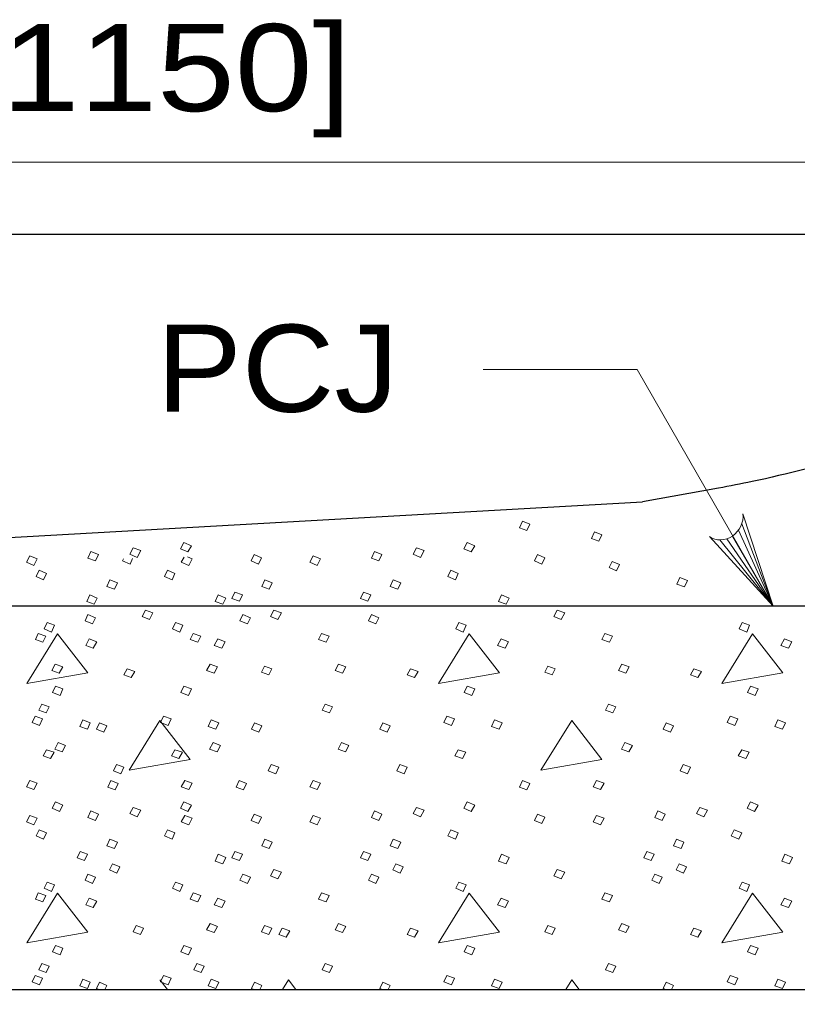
# Model space of a CAD drawing. Extents: x -1431.2 to -1397.2, y -1045.1 to -1001.1.
# Drawn here: x -1423.56 to -1422.141, y -1043.619 to -1041.85 of the extents above; entities that cross this region are included whole.
import ezdxf

# ---------------------------------------------------------------- set-up
doc = ezdxf.new("R2010")
doc.units = 0
doc.header["$LTSCALE"] = 0.064
doc.layers.add('1', color=7, linetype='Continuous', lineweight=13)

msp = doc.modelspace()

# ---------------------------------------------------------------- linework, layer by layer
at = {"layer": '1'}
for p, q in [((-1421.35642, -1042.111), (-1425.81283, -1042.111)), ((-1422.43383, -1042.48883), (-1422.71458, -1042.48883)), ((-1422.18592, -1042.9205), (-1422.43383, -1042.48883)), ((-1422.24292, -1042.77033), (-1422.18592, -1042.9205)), ((-1422.27042, -1042.79767), (-1422.18592, -1042.9205)), ((-1422.25992, -1042.79242), (-1422.18592, -1042.9205)), ((-1422.24883, -1042.78158), (-1422.18592, -1042.9205)), ((-1422.28267, -1042.79958), (-1422.18592, -1042.9205)), ((-1423.29, -1043.61933), (-1423.30367, -1043.60183)), ((-1423.0695, -1043.60183), (-1423.08042, -1043.61933)), ((-1423.05592, -1043.61933), (-1423.0695, -1043.60183)), ((-1422.553, -1043.60183), (-1422.56392, -1043.61933)), ((-1422.53942, -1043.61933), (-1422.553, -1043.60183))]:
    msp.add_line(p, q, dxfattribs=at)
at = {"layer": '1', "lineweight": 25}
for p, q in [((-1422.28533, -1042.70533), (-1422.42375, -1042.73033)), ((-1425.81283, -1042.9205), (-1422.42375, -1042.73033)), ((-1420.649, -1042.9205), (-1425.81283, -1042.9205))]:
    msp.add_line(p, q, dxfattribs=at)
for points in [[(-1421.35642, -1042.24275), (-1422.37992, -1042.24275), (-1425.79833, -1042.24275)], [(-1426.53858, -1043.13475), (-1426.53858, -1043.61933), (-1420.649, -1043.61933)]]:
    msp.add_lwpolyline(points, dxfattribs=at)
at = {"layer": '1'}
for points in [[(-1422.241, -1042.75167), (-1422.18592, -1042.9205), (-1422.30192, -1042.79317)], [(-1423.25333, -1042.83058), (-1423.24475, -1042.83367), (-1423.25108, -1042.84592), (-1423.26467, -1042.84017), (-1423.25942, -1042.83075)], [(-1423.35333, -1042.83358), (-1423.358, -1042.84342), (-1423.37158, -1042.83775), (-1423.36992, -1042.83408)], [(-1423.41467, -1043.61933), (-1423.41933, -1043.61733), (-1423.41392, -1043.60592)], [(-1423.41392, -1043.60592), (-1423.40033, -1043.61167), (-1423.40392, -1043.61933)], [(-1423.13225, -1043.61933), (-1423.13692, -1043.61733), (-1423.1315, -1043.60592)], [(-1423.1315, -1043.60592), (-1423.11783, -1043.61167), (-1423.1215, -1043.61933)], [(-1422.89817, -1043.61933), (-1422.90283, -1043.61733), (-1422.89733, -1043.60592)], [(-1422.89733, -1043.60592), (-1422.88375, -1043.61167), (-1422.88742, -1043.61933)], [(-1422.38167, -1043.61933), (-1422.38625, -1043.61733), (-1422.38083, -1043.60592)], [(-1422.38083, -1043.60592), (-1422.36725, -1043.61167), (-1422.37083, -1043.61933)]]:
    msp.add_lwpolyline(points, dxfattribs=at)
for points in [[(-1422.64275, -1042.76517), (-1422.62917, -1042.77092), (-1422.63458, -1042.78233), (-1422.64817, -1042.77742)], [(-1422.51142, -1042.78483), (-1422.49783, -1042.7905), (-1422.50325, -1042.80192), (-1422.51683, -1042.797)], [(-1423.35225, -1042.81408), (-1423.33867, -1042.819), (-1423.345, -1042.83125), (-1423.35858, -1042.8255)], [(-1423.25983, -1042.80433), (-1423.24625, -1042.81), (-1423.25258, -1042.82142), (-1423.26617, -1042.81575)], [(-1422.83575, -1042.81408), (-1422.82217, -1042.819), (-1422.8285, -1042.83125), (-1422.84208, -1042.8255)], [(-1422.74333, -1042.80433), (-1422.72975, -1042.81), (-1422.73608, -1042.82142), (-1422.74967, -1042.81575)], [(-1423.54075, -1042.82875), (-1423.52717, -1042.83367), (-1423.5335, -1042.84592), (-1423.54708, -1042.84017)], [(-1423.42933, -1042.82058), (-1423.41567, -1042.82633), (-1423.42117, -1042.83775), (-1423.43475, -1042.83283)], [(-1423.13208, -1042.82633), (-1423.1185, -1042.832), (-1423.12392, -1042.84342), (-1423.1375, -1042.83775)], [(-1423.02425, -1042.82875), (-1423.01067, -1042.83367), (-1423.017, -1042.84592), (-1423.03058, -1042.84017)], [(-1422.91275, -1042.82058), (-1422.89917, -1042.82633), (-1422.90458, -1042.83775), (-1422.91817, -1042.83283)], [(-1422.61558, -1042.82633), (-1422.60192, -1042.832), (-1422.60742, -1042.84342), (-1422.621, -1042.83775)], [(-1422.47933, -1042.83858), (-1422.46575, -1042.84433), (-1422.47117, -1042.85575), (-1422.48475, -1042.85)], [(-1423.52383, -1042.85483), (-1423.51025, -1042.86058), (-1423.51567, -1042.872), (-1423.52925, -1042.86625)], [(-1423.28975, -1042.85483), (-1423.27617, -1042.86058), (-1423.28158, -1042.872), (-1423.29517, -1042.86625)], [(-1422.77325, -1042.85483), (-1422.75967, -1042.86058), (-1422.76508, -1042.872), (-1422.77867, -1042.86625)], [(-1422.35567, -1042.86783), (-1422.34208, -1042.8735), (-1422.3475, -1042.88492), (-1422.36108, -1042.88008)], [(-1423.39483, -1042.872), (-1423.38125, -1042.87767), (-1423.38667, -1042.88908), (-1423.40033, -1042.88425)], [(-1423.11242, -1042.872), (-1423.09883, -1042.87767), (-1423.10425, -1042.88908), (-1423.11783, -1042.88425)], [(-1422.87833, -1042.872), (-1422.86475, -1042.87767), (-1422.87017, -1042.88908), (-1422.88375, -1042.88425)], [(-1423.43142, -1042.89975), (-1423.41783, -1042.90542), (-1423.42325, -1042.91683), (-1423.43683, -1042.91192)], [(-1423.19733, -1042.89975), (-1423.18375, -1042.90542), (-1423.18917, -1042.91683), (-1423.20275, -1042.91192)], [(-1423.16683, -1042.89483), (-1423.15325, -1042.89975), (-1423.15867, -1042.91117), (-1423.17225, -1042.90625)], [(-1422.93267, -1042.89483), (-1422.91908, -1042.89975), (-1422.92458, -1042.91117), (-1422.93817, -1042.90625)], [(-1422.68075, -1042.89975), (-1422.66717, -1042.90542), (-1422.67267, -1042.91683), (-1422.68625, -1042.91192)], [(-1423.43475, -1042.93558), (-1423.42117, -1042.94133), (-1423.42658, -1042.95275), (-1423.44017, -1042.947)], [(-1423.32992, -1042.92742), (-1423.31633, -1042.93233), (-1423.32267, -1042.94458), (-1423.33625, -1042.93883)], [(-1423.15233, -1042.93558), (-1423.13875, -1042.94133), (-1423.14417, -1042.95275), (-1423.15775, -1042.947)], [(-1423.09583, -1042.92742), (-1423.08225, -1042.93233), (-1423.08858, -1042.94458), (-1423.10217, -1042.93883)], [(-1422.91817, -1042.93558), (-1422.90458, -1042.94133), (-1422.91008, -1042.95275), (-1422.92367, -1042.947)], [(-1422.57925, -1042.92742), (-1422.56567, -1042.93233), (-1422.57208, -1042.94458), (-1422.58567, -1042.93883)], [(-1423.50933, -1042.95025), (-1423.49575, -1042.95517), (-1423.50117, -1042.96742), (-1423.51475, -1042.96167)], [(-1423.27525, -1042.95025), (-1423.26167, -1042.95517), (-1423.26708, -1042.96742), (-1423.28067, -1042.96167)], [(-1422.75875, -1042.95025), (-1422.74517, -1042.95517), (-1422.75058, -1042.96742), (-1422.76417, -1042.96167)], [(-1422.24217, -1042.95025), (-1422.22858, -1042.95517), (-1422.234, -1042.96742), (-1422.24767, -1042.96167)], [(-1423.49033, -1042.97067), (-1423.5465, -1043.06117), (-1423.435, -1043.04158)], [(-1423.52533, -1042.96983), (-1423.51175, -1042.97475), (-1423.51717, -1042.98617), (-1423.53075, -1042.98125)], [(-1423.24292, -1042.96983), (-1423.22933, -1042.97475), (-1423.23475, -1042.98617), (-1423.24833, -1042.98125)], [(-1423.00883, -1042.96983), (-1422.99525, -1042.97475), (-1423.00067, -1042.98617), (-1423.01425, -1042.98125)], [(-1422.73967, -1042.97067), (-1422.79583, -1043.06117), (-1422.68442, -1043.04158)], [(-1422.49233, -1042.96983), (-1422.47867, -1042.97475), (-1422.48417, -1042.98617), (-1422.49775, -1042.98125)], [(-1422.22317, -1042.97067), (-1422.27933, -1043.06117), (-1422.16792, -1043.04158)], [(-1423.43233, -1042.97967), (-1423.41875, -1042.98533), (-1423.42508, -1042.99675), (-1423.43867, -1042.99183)], [(-1423.19825, -1042.97967), (-1423.18467, -1042.98533), (-1423.191, -1042.99675), (-1423.20458, -1042.99183)], [(-1422.68167, -1042.97967), (-1422.66808, -1042.98533), (-1422.67442, -1042.99675), (-1422.688, -1042.99183)], [(-1422.16517, -1042.97967), (-1422.15158, -1042.98533), (-1422.15792, -1042.99675), (-1422.1715, -1042.99183)], [(-1423.4945, -1043.02608), (-1423.48092, -1043.031), (-1423.48733, -1043.04242), (-1423.50092, -1043.0375)], [(-1423.21208, -1043.02608), (-1423.1985, -1043.031), (-1423.20483, -1043.04242), (-1423.21842, -1043.0375)], [(-1422.978, -1043.02608), (-1422.96442, -1043.031), (-1422.97075, -1043.04242), (-1422.98433, -1043.0375)], [(-1422.4615, -1043.02608), (-1422.44792, -1043.031), (-1422.45425, -1043.04242), (-1422.46783, -1043.0375)], [(-1423.36317, -1043.03425), (-1423.34958, -1043.03917), (-1423.35592, -1043.05058), (-1423.3695, -1043.04567)], [(-1423.113, -1043.02942), (-1423.09942, -1043.03425), (-1423.10492, -1043.04567), (-1423.1185, -1043.04083)], [(-1422.84667, -1043.03425), (-1422.833, -1043.03917), (-1422.83933, -1043.05058), (-1422.853, -1043.04567)], [(-1422.5965, -1043.02942), (-1422.58292, -1043.03425), (-1422.58833, -1043.04567), (-1422.60192, -1043.04083)], [(-1422.33008, -1043.03425), (-1422.3165, -1043.03917), (-1422.32283, -1043.05058), (-1422.33642, -1043.04567)], [(-1423.49392, -1043.06608), (-1423.48033, -1043.071), (-1423.48575, -1043.08317), (-1423.49933, -1043.0775)], [(-1423.25983, -1043.06608), (-1423.24625, -1043.071), (-1423.25167, -1043.08317), (-1423.26525, -1043.0775)], [(-1422.74333, -1043.06608), (-1422.72975, -1043.071), (-1422.73517, -1043.08317), (-1422.74875, -1043.0775)], [(-1422.22675, -1043.06608), (-1422.21317, -1043.071), (-1422.21867, -1043.08317), (-1422.23225, -1043.0775)], [(-1423.519, -1043.09867), (-1423.50542, -1043.10358), (-1423.51083, -1043.115), (-1423.52442, -1043.11008)], [(-1423.0025, -1043.09867), (-1422.98892, -1043.10358), (-1422.99433, -1043.115), (-1423.00792, -1043.11008)], [(-1422.486, -1043.09867), (-1422.47233, -1043.10358), (-1422.47783, -1043.115), (-1422.49142, -1043.11008)], [(-1423.53108, -1043.12075), (-1423.5175, -1043.12558), (-1423.52292, -1043.13783), (-1423.5365, -1043.13217)], [(-1423.44408, -1043.12725), (-1423.4305, -1043.13292), (-1423.43592, -1043.14433), (-1423.4495, -1043.1395)], [(-1423.41392, -1043.13292), (-1423.40033, -1043.13867), (-1423.40575, -1043.15008), (-1423.41933, -1043.14433)], [(-1423.30367, -1043.12883), (-1423.35983, -1043.21942), (-1423.24833, -1043.19983)], [(-1423.297, -1043.12075), (-1423.28342, -1043.12558), (-1423.28883, -1043.13783), (-1423.30242, -1043.13217)], [(-1423.21, -1043.12725), (-1423.19642, -1043.13292), (-1423.20183, -1043.14433), (-1423.21542, -1043.1395)], [(-1423.1315, -1043.13292), (-1423.11783, -1043.13867), (-1423.12333, -1043.15008), (-1423.13692, -1043.14433)], [(-1422.89733, -1043.13292), (-1422.88375, -1043.13867), (-1422.88917, -1043.15008), (-1422.90283, -1043.14433)], [(-1422.7805, -1043.12075), (-1422.76683, -1043.12558), (-1422.77233, -1043.13783), (-1422.78592, -1043.13217)], [(-1422.6935, -1043.12725), (-1422.67992, -1043.13292), (-1422.68533, -1043.14433), (-1422.69892, -1043.1395)], [(-1422.553, -1043.12883), (-1422.60917, -1043.21942), (-1422.49775, -1043.19983)], [(-1422.38083, -1043.13292), (-1422.36725, -1043.13867), (-1422.37267, -1043.15008), (-1422.38625, -1043.14433)], [(-1422.26392, -1043.12075), (-1422.25033, -1043.12558), (-1422.25575, -1043.13783), (-1422.26942, -1043.13217)], [(-1422.17692, -1043.12725), (-1422.16333, -1043.13292), (-1422.16883, -1043.14433), (-1422.18242, -1043.1395)], [(-1423.48908, -1043.16883), (-1423.4755, -1043.17458), (-1423.48183, -1043.186), (-1423.49542, -1043.18108)], [(-1423.20667, -1043.16883), (-1423.19308, -1043.17458), (-1423.19942, -1043.186), (-1423.213, -1043.18108)], [(-1422.97258, -1043.16883), (-1422.959, -1043.17458), (-1422.96533, -1043.186), (-1422.97892, -1043.18108)], [(-1422.45608, -1043.16883), (-1422.44242, -1043.17458), (-1422.44883, -1043.186), (-1422.46242, -1043.18108)], [(-1423.51025, -1043.18192), (-1423.49667, -1043.18675), (-1423.503, -1043.19817), (-1423.51658, -1043.19325)], [(-1423.27617, -1043.18192), (-1423.26258, -1043.18675), (-1423.26892, -1043.19817), (-1423.2825, -1043.19325)], [(-1422.75967, -1043.18192), (-1422.746, -1043.18675), (-1422.75233, -1043.19817), (-1422.766, -1043.19325)], [(-1422.24308, -1043.18192), (-1422.2295, -1043.18675), (-1422.23583, -1043.19817), (-1422.24942, -1043.19325)], [(-1423.38308, -1043.20875), (-1423.3695, -1043.21367), (-1423.37492, -1043.22592), (-1423.3885, -1043.22025)], [(-1423.10067, -1043.20875), (-1423.08708, -1043.21367), (-1423.0925, -1043.22592), (-1423.10608, -1043.22025)], [(-1422.86658, -1043.20875), (-1422.853, -1043.21367), (-1422.85842, -1043.22592), (-1422.872, -1043.22025)], [(-1422.35, -1043.20875), (-1422.33642, -1043.21367), (-1422.34192, -1043.22592), (-1422.3555, -1043.22025)], [(-1423.54075, -1043.23817), (-1423.52717, -1043.243), (-1423.5335, -1043.25442), (-1423.54708, -1043.24958)], [(-1423.39333, -1043.23817), (-1423.37975, -1043.24383), (-1423.38517, -1043.25525), (-1423.39875, -1043.25042)], [(-1423.25833, -1043.23817), (-1423.24475, -1043.243), (-1423.25108, -1043.25442), (-1423.26467, -1043.24958)], [(-1423.15925, -1043.23817), (-1423.14567, -1043.24383), (-1423.15108, -1043.25525), (-1423.16467, -1043.25042)], [(-1423.02425, -1043.23817), (-1423.01067, -1043.243), (-1423.017, -1043.25442), (-1423.03058, -1043.24958)], [(-1422.64275, -1043.23817), (-1422.62917, -1043.24383), (-1422.63458, -1043.25525), (-1422.64817, -1043.25042)], [(-1422.50775, -1043.23817), (-1422.49408, -1043.243), (-1422.50042, -1043.25442), (-1422.51408, -1043.24958)], [(-1423.49392, -1043.27725), (-1423.48033, -1043.283), (-1423.48667, -1043.29442), (-1423.50025, -1043.28867)], [(-1423.35225, -1043.28708), (-1423.33867, -1043.292), (-1423.345, -1043.30417), (-1423.35858, -1043.2985)], [(-1423.25983, -1043.27725), (-1423.24625, -1043.283), (-1423.25258, -1043.29442), (-1423.26617, -1043.28867)], [(-1422.83575, -1043.28708), (-1422.82217, -1043.292), (-1422.8285, -1043.30417), (-1422.84208, -1043.2985)], [(-1422.74333, -1043.27725), (-1422.72975, -1043.283), (-1422.73608, -1043.29442), (-1422.74967, -1043.28867)], [(-1422.31925, -1043.28708), (-1422.30558, -1043.292), (-1422.312, -1043.30417), (-1422.32558, -1043.2985)], [(-1422.22675, -1043.27725), (-1422.21317, -1043.283), (-1422.2195, -1043.29442), (-1422.23317, -1043.28867)], [(-1423.54075, -1043.30175), (-1423.52717, -1043.30667), (-1423.5335, -1043.31892), (-1423.54708, -1043.31317)], [(-1423.42933, -1043.29358), (-1423.41567, -1043.29933), (-1423.42117, -1043.31075), (-1423.43475, -1043.30583)], [(-1423.25833, -1043.30175), (-1423.24475, -1043.30667), (-1423.25108, -1043.31892), (-1423.26467, -1043.31317)], [(-1423.13208, -1043.29933), (-1423.1185, -1043.305), (-1423.12392, -1043.31642), (-1423.1375, -1043.31075)], [(-1423.02425, -1043.30175), (-1423.01067, -1043.30667), (-1423.017, -1043.31892), (-1423.03058, -1043.31317)], [(-1422.91275, -1043.29358), (-1422.89917, -1043.29933), (-1422.90458, -1043.31075), (-1422.91817, -1043.30583)], [(-1422.61558, -1043.29933), (-1422.60192, -1043.305), (-1422.60742, -1043.31642), (-1422.621, -1043.31075)], [(-1422.50775, -1043.30175), (-1422.49408, -1043.30667), (-1422.50042, -1043.31892), (-1422.51408, -1043.31317)], [(-1422.39625, -1043.29358), (-1422.38267, -1043.29933), (-1422.38808, -1043.31075), (-1422.40167, -1043.30583)], [(-1423.52383, -1043.32783), (-1423.51025, -1043.33358), (-1423.51567, -1043.345), (-1423.52925, -1043.33925)], [(-1423.28975, -1043.32783), (-1423.27617, -1043.33358), (-1423.28158, -1043.345), (-1423.29517, -1043.33925)], [(-1422.77325, -1043.32783), (-1422.75967, -1043.33358), (-1422.76508, -1043.345), (-1422.77867, -1043.33925)], [(-1422.25667, -1043.32783), (-1422.24308, -1043.33358), (-1422.2485, -1043.345), (-1422.26217, -1043.33925)], [(-1423.39483, -1043.345), (-1423.38125, -1043.35067), (-1423.38667, -1043.36208), (-1423.40033, -1043.35717)], [(-1423.11242, -1043.345), (-1423.09883, -1043.35067), (-1423.10425, -1043.36208), (-1423.11783, -1043.35717)], [(-1422.87833, -1043.345), (-1422.86475, -1043.35067), (-1422.87017, -1043.36208), (-1422.88375, -1043.35717)], [(-1422.36183, -1043.345), (-1422.34825, -1043.35067), (-1422.35367, -1043.36208), (-1422.36725, -1043.35717)], [(-1423.44925, -1043.36783), (-1423.43567, -1043.37267), (-1423.44108, -1043.38408), (-1423.45467, -1043.37925)], [(-1423.19733, -1043.37267), (-1423.18375, -1043.37842), (-1423.18917, -1043.38983), (-1423.20275, -1043.38492)], [(-1423.16683, -1043.36783), (-1423.15325, -1043.37267), (-1423.15867, -1043.38408), (-1423.17225, -1043.37925)], [(-1422.93267, -1043.36783), (-1422.91908, -1043.37267), (-1422.92458, -1043.38408), (-1422.93817, -1043.37925)], [(-1422.68075, -1043.37267), (-1422.66717, -1043.37842), (-1422.67267, -1043.38983), (-1422.68625, -1043.38492)], [(-1422.41617, -1043.36783), (-1422.40258, -1043.37267), (-1422.408, -1043.38408), (-1422.42158, -1043.37925)], [(-1422.16425, -1043.37267), (-1422.15067, -1043.37842), (-1422.15608, -1043.38983), (-1422.16967, -1043.38492)], [(-1423.39033, -1043.38983), (-1423.37675, -1043.3955), (-1423.38217, -1043.40692), (-1423.39575, -1043.40125)], [(-1422.87383, -1043.38983), (-1422.86025, -1043.3955), (-1422.86567, -1043.40692), (-1422.87925, -1043.40125)], [(-1422.35725, -1043.38983), (-1422.34367, -1043.3955), (-1422.34917, -1043.40692), (-1422.36275, -1043.40125)], [(-1423.43475, -1043.40858), (-1423.42117, -1043.41433), (-1423.42658, -1043.42575), (-1423.44017, -1043.42)], [(-1423.15233, -1043.40858), (-1423.13875, -1043.41433), (-1423.14417, -1043.42575), (-1423.15775, -1043.42)], [(-1423.09583, -1043.40042), (-1423.08225, -1043.40533), (-1423.08858, -1043.41758), (-1423.10217, -1043.41183)], [(-1422.91817, -1043.40858), (-1422.90458, -1043.41433), (-1422.91008, -1043.42575), (-1422.92367, -1043.42)], [(-1422.57925, -1043.40042), (-1422.56567, -1043.40533), (-1422.57208, -1043.41758), (-1422.58567, -1043.41183)], [(-1422.40167, -1043.40858), (-1422.38808, -1043.41433), (-1422.3935, -1043.42575), (-1422.40708, -1043.42)], [(-1423.50933, -1043.42325), (-1423.49575, -1043.42817), (-1423.50117, -1043.44042), (-1423.51475, -1043.43467)], [(-1423.27525, -1043.42325), (-1423.26167, -1043.42817), (-1423.26708, -1043.44042), (-1423.28067, -1043.43467)], [(-1422.75875, -1043.42325), (-1422.74517, -1043.42817), (-1422.75058, -1043.44042), (-1422.76417, -1043.43467)], [(-1422.24217, -1043.42325), (-1422.22858, -1043.42817), (-1422.234, -1043.44042), (-1422.24767, -1043.43467)], [(-1423.49033, -1043.44367), (-1423.5465, -1043.53417), (-1423.435, -1043.51458)], [(-1423.52533, -1043.44283), (-1423.51175, -1043.44775), (-1423.51717, -1043.45917), (-1423.53075, -1043.45425)], [(-1423.24292, -1043.44283), (-1423.22933, -1043.44775), (-1423.23475, -1043.45917), (-1423.24833, -1043.45425)], [(-1423.00883, -1043.44283), (-1422.99525, -1043.44775), (-1423.00067, -1043.45917), (-1423.01425, -1043.45425)], [(-1422.73967, -1043.44367), (-1422.79583, -1043.53417), (-1422.68442, -1043.51458)], [(-1422.49233, -1043.44283), (-1422.47867, -1043.44775), (-1422.48417, -1043.45917), (-1422.49775, -1043.45425)], [(-1422.22317, -1043.44367), (-1422.27933, -1043.53417), (-1422.16792, -1043.51458)], [(-1423.43233, -1043.45258), (-1423.41875, -1043.45833), (-1423.42508, -1043.46975), (-1423.43867, -1043.46483)], [(-1423.19825, -1043.45258), (-1423.18467, -1043.45833), (-1423.191, -1043.46975), (-1423.20458, -1043.46483)], [(-1422.68167, -1043.45258), (-1422.66808, -1043.45833), (-1422.67442, -1043.46975), (-1422.688, -1043.46483)], [(-1422.16517, -1043.45258), (-1422.15158, -1043.45833), (-1422.15792, -1043.46975), (-1422.1715, -1043.46483)], [(-1423.34717, -1043.50233), (-1423.33358, -1043.50725), (-1423.339, -1043.51867), (-1423.35258, -1043.51375)], [(-1423.21208, -1043.49908), (-1423.1985, -1043.504), (-1423.20483, -1043.51542), (-1423.21842, -1043.5105)], [(-1423.113, -1043.50233), (-1423.09942, -1043.50725), (-1423.10492, -1043.51867), (-1423.1185, -1043.51375)], [(-1422.978, -1043.49908), (-1422.96442, -1043.504), (-1422.97075, -1043.51542), (-1422.98433, -1043.5105)], [(-1422.5965, -1043.50233), (-1422.58292, -1043.50725), (-1422.58833, -1043.51867), (-1422.60192, -1043.51375)], [(-1422.4615, -1043.49908), (-1422.44792, -1043.504), (-1422.45425, -1043.51542), (-1422.46783, -1043.5105)], [(-1423.08075, -1043.50725), (-1423.06708, -1043.51217), (-1423.0735, -1043.52358), (-1423.08708, -1043.51867)], [(-1422.84667, -1043.50725), (-1422.833, -1043.51217), (-1422.83933, -1043.52358), (-1422.853, -1043.51867)], [(-1422.33008, -1043.50725), (-1422.3165, -1043.51217), (-1422.32283, -1043.52358), (-1422.33642, -1043.51867)], [(-1423.49392, -1043.53908), (-1423.48033, -1043.54392), (-1423.48575, -1043.55617), (-1423.49933, -1043.5505)], [(-1423.25983, -1043.53908), (-1423.24625, -1043.54392), (-1423.25167, -1043.55617), (-1423.26525, -1043.5505)], [(-1422.74333, -1043.53908), (-1422.72975, -1043.54392), (-1422.73517, -1043.55617), (-1422.74875, -1043.5505)], [(-1422.22675, -1043.53908), (-1422.21317, -1043.54392), (-1422.21867, -1043.55617), (-1422.23225, -1043.5505)], [(-1423.519, -1043.57167), (-1423.50542, -1043.57658), (-1423.51083, -1043.588), (-1423.52442, -1043.58308)], [(-1423.23658, -1043.57167), (-1423.223, -1043.57658), (-1423.22842, -1043.588), (-1423.242, -1043.58308)], [(-1423.0025, -1043.57167), (-1422.98892, -1043.57658), (-1422.99433, -1043.588), (-1423.00792, -1043.58308)], [(-1422.486, -1043.57167), (-1422.47233, -1043.57658), (-1422.47783, -1043.588), (-1422.49142, -1043.58308)], [(-1423.53108, -1043.59367), (-1423.5175, -1043.59858), (-1423.52292, -1043.61083), (-1423.5365, -1043.60508)], [(-1423.44408, -1043.60025), (-1423.4305, -1043.60592), (-1423.43592, -1043.61733), (-1423.4495, -1043.61242)], [(-1423.297, -1043.59367), (-1423.28342, -1043.59858), (-1423.28883, -1043.61083), (-1423.30242, -1043.60508)], [(-1423.21, -1043.60025), (-1423.19642, -1043.60592), (-1423.20183, -1043.61733), (-1423.21542, -1043.61242)], [(-1422.7805, -1043.59367), (-1422.76683, -1043.59858), (-1422.77233, -1043.61083), (-1422.78592, -1043.60508)], [(-1422.6935, -1043.60025), (-1422.67992, -1043.60592), (-1422.68533, -1043.61733), (-1422.69892, -1043.61242)], [(-1422.26392, -1043.59367), (-1422.25033, -1043.59858), (-1422.25575, -1043.61083), (-1422.26942, -1043.60508)], [(-1422.17692, -1043.60025), (-1422.16333, -1043.60592), (-1422.16883, -1043.61733), (-1422.18242, -1043.61242)]]:
    msp.add_lwpolyline(points, close=True, dxfattribs=at)
msp.add_ellipse((-1422.27838, -1042.76043), major_axis=(-0.02342, -0.03284), ratio=0.899905, start_param=6.2796095, end_param=8.6502227, dxfattribs=at)
at = {"layer": '1', "lineweight": 25}
msp.add_spline([(-1421.35642, -1042.24275), (-1421.56458, -1042.41417), (-1421.84675, -1042.57292), (-1422.224, -1042.69308), (-1422.28533, -1042.70533)], degree=3, dxfattribs=at)

# ---------------------------------------------------------------- texts
at = {"layer": '1'}
for s, width, p in [('3\'-10" [1150]', 1.2, (-1424.383, -1042.01775)), ('PCJ', 1.1, (-1423.31008, -1042.56592))]:
    msp.add_text(s, height=0.1588, dxfattribs=dict(at, width=width)).set_placement(p)

doc.saveas('drawing.dxf')
